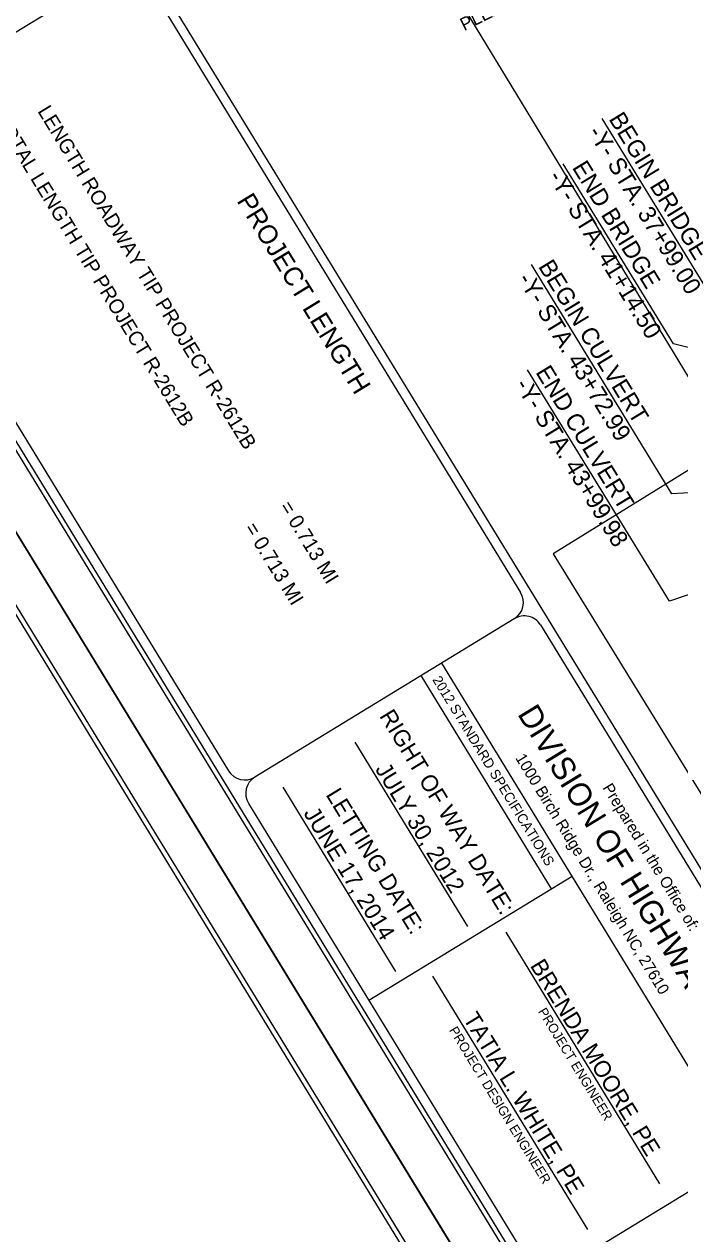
# Model space of a CAD drawing. Extents: x 1750583 to 1791140, y 783580 to 827376.
# Drawn here: x 1775731 to 1779520, y 808725 to 815720 of the extents above; entities that cross this region are included whole.
import ezdxf

# ---------------------------------------------------------------- set-up
doc = ezdxf.new("R2010")
doc.units = 0
for name, color, linetype in [('COGO Default Parcel', 7, 'Continuous'), ('Prop Dimension Text', 7, 'Continuous'), ('Sheet Clip Boundary CELL', 7, 'Continuous'), ('Sheet Cutting Line CELL', 7, 'Continuous'), ('Sheet Data Field CELL', 7, 'Continuous'), ('Sheet Plan CELL', 7, 'Continuous'), ('Sheet Plot Border Inside CELL', 7, 'Continuous'), ('Sheet Plot Border Outside CELL', 7, 'Continuous'), ('Sheet Title CELL', 7, 'Continuous')]:
    doc.layers.add(name, color=color, linetype=linetype)

msp = doc.modelspace()

# ---------------------------------------------------------------- linework, layer by layer
at = {"layer": 'COGO Default Parcel'}
for p, q in [((1779745.8, 814074.3), (1779070.7, 815175.4)), ((1779484.8, 813871.7), (1778846.4, 814913.1)), ((1779475.1, 813004.6), (1778662.3, 814330.4)), ((1781749.3, 813311.1), (1779484.8, 813871.7)), ((1779460.8, 812384.2), (1778640.6, 813722.1)), ((1781579.6, 813096.7), (1779460.8, 812384.2)), ((1781595.3, 813116.5), (1779475.1, 813004.6))]:
    msp.add_line(p, q, dxfattribs=at)
at = {"layer": 'Sheet Clip Boundary CELL'}
msp.add_lwpolyline([(1778136.8, 816039.3), (1779807.6, 813286.9), (1778788.4, 812657.1), (1781190.7, 808756.5), (1783067.6, 810931.3), (1785138.2, 813464), (1782097.7, 818459.4)], close=True, dxfattribs=at)
at = {"layer": 'Sheet Cutting Line CELL'}
for p, q in [((1771176.2, 820157.4), (1780824.8, 804365.9)), ((1780822, 804370.5), (1771176.2, 820157.4))]:
    msp.add_line(p, q, dxfattribs=at)
at = {"layer": 'Sheet Plan CELL'}
msp.add_lwpolyline([(1780513.6, 804401), (1771919.2, 818467.1), (1762073, 812451), (1770667.3, 798385)], close=True, dxfattribs=at)
at = {"layer": 'Sheet Plot Border Inside CELL'}
for points in [[(1771461.1, 820164), (1781009.5, 804536.6), (1790903.5, 810581.9), (1781355.2, 826209.3)], [(1761170, 813876.1), (1770715.5, 798253.4), (1780608.6, 804298.1), (1771063.2, 819920.9)]]:
    msp.add_lwpolyline(points, close=True, dxfattribs=at)
at = {"layer": 'Sheet Plot Border Outside CELL'}
for points in [[(1791139.8, 810668.3), (1781491.2, 826459.8), (1771176.2, 820157.4), (1780824.8, 804365.9)], [(1760908, 813883.5), (1770553.7, 798096.7), (1780822, 804370.5), (1771176.2, 820157.4)]]:
    msp.add_lwpolyline(points, close=True, dxfattribs=at)
at = {"layer": 'Sheet Title CELL'}
for p, q in [((1774521.6, 819213.7), (1782657.6, 805897.8)), ((1776271.7, 816033.2), (1774771.3, 815116.5)), ((1776422.7, 815996.6), (1778599.9, 812433.2)), ((1778563.6, 812282.2), (1777063.2, 811365.5)), ((1778714.6, 812245.8), (1780347.6, 809573.2)), ((1779891.3, 809165.7), (1778143.9, 812025.8)), ((1778778, 810719.1), (1778024.4, 811952.8)), ((1778295, 810501.3), (1777643.3, 811568)), ((1777879.1, 810242), (1777227.3, 811308.7)), ((1778560.9, 811074.6), (1778560.9, 811074.6)), ((1777968.9, 811034.8), (1777968.9, 811034.8)), ((1778897.6, 810792.2), (1777723.1, 810074.6)), ((1778515.2, 810469.7), (1779404, 809014.7)), ((1778091.2, 810215.2), (1778986.5, 808749.9)), ((1778810.6, 808505.3), (1780311, 809422.1))]:
    msp.add_line(p, q, dxfattribs=at)
for points in [[(1772424.7, 818640.7), (1780904.5, 804762.2)], [(1774734.7, 814965.3), (1776912, 811401.9)], [(1777026.7, 811214.4), (1778659.5, 808541.8)]]:
    msp.add_lwpolyline(points, dxfattribs=at)
for centre, start, end in [((1778506.7, 812376.2), 301.42495, 31.42495), ((1778621.3, 812188.7), 31.42495, 121.42495), ((1777006.3, 811459.5), 211.42495, 301.42495), ((1777120.9, 811271.9), 121.42495, 211.42495)]:
    msp.add_arc(centre, 109.9, start, end, dxfattribs=at)

# ---------------------------------------------------------------- texts
at = {"layer": 'Prop Dimension Text'}
for s, height, rotation, p in [('PLEASANT GARDEN', 75, 26.20646, (1778273.7, 815679.5)), ('BEGIN BRIDGE', 100, 301.40172, (1779107, 815172.3)), ('-Y- STA. 37+99.00', 100, 301.40172, (1778986, 815095.6)), ('END BRIDGE', 100, 301.40172, (1778895.2, 814891.7)), ('-Y- STA. 41+14.50', 100, 301.40172, (1778756.7, 814838.6)), ('BEGIN CULVERT', 100, 301.40172, (1778699.3, 814319.4)), ('-Y- STA. 43+72.99', 100, 301.40172, (1778579.8, 814246.5)), ('END CULVERT', 100, 301.40172, (1778684, 813707.7)), ('-Y- STA. 43+99.98', 100, 301.40172, (1778564.5, 813634.8))]:
    msp.add_text(s, height=height, rotation=rotation, dxfattribs=at).set_placement(p)
at = {"layer": 'Sheet Data Field CELL'}
for s, height, p in [('LENGTH ROADWAY TIP PROJECT R-2612B', 83.997, (1775805.3, 815217.6)), ('      TOTAL LENGTH TIP PROJECT R-2612B', 83.997, (1775461, 815323.7)), ('= 0.713 MI', 84, (1777203.6, 812930.8)), ('= 0.713 MI', 84, (1777000.8, 812806.9)), ('JULY 30, 2012', 96.251, (1777756.4, 811412)), ('JUNE 17, 2014     ', 96.251, (1777342.5, 811157.2)), ('BRENDA MOORE, PE', 96.251, (1778652.2, 810275.9)), ('TATIA L. WHITE, PE          ', 96.251, (1778265.3, 809969.4))]:
    msp.add_text(s, height=height, rotation=301.42495, dxfattribs=at).set_placement(p)
at = {"layer": 'Sheet Title CELL'}
for s, height, p in [('PROJECT LENGTH', 109.888, (1776956.3, 814698.8)), ('2012 STANDARD SPECIFICATIONS', 57.144, (1778088.2, 811929.4)), ('RIGHT OF WAY DATE: ', 96.154, (1777781, 811719.8)), ('DIVISION OF HIGHWAYS', 133.928, (1778578.8, 811731.5)), ('1000 Birch Ridge Dr., Raleigh NC, 27610', 65.935, (1778567.2, 811477.5)), ('Prepared in the Office of:', 65.929, (1779071.2, 811304.6)), ('LETTING DATE:', 96.154, (1777471.3, 811264.6)), ('PROJECT ENGINEER', 54.941, (1778699, 810010.8)), ('PROJECT DESIGN ENGINEER', 54.941, (1778184.7, 809902.7))]:
    msp.add_text(s, height=height, rotation=301.42495, dxfattribs=at).set_placement(p)

doc.saveas('drawing.dxf')
